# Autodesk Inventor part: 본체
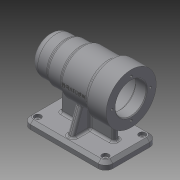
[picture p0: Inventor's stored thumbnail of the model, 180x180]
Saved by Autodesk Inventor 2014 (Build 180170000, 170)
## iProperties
Created: 2016-06
Part Number: 본체
Material: 일반
Document SubType Name: Modeling
Designer: SEC
Density: 1 g/cm^3
Appearance: 기본값
Author: SEC
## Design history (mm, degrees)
sketch "스케치1" dims "d24" = 3
  geometry: L1 (-56, 0)-(56, 0); L2 (-56, 0)-(-56, 15); L3 (-46, 25)-(-31, 25); L4 (-31, 25)-(-31, 27); L5 (-31, 27)-(-11, 27); L6 (-11, 27)-(-11, 30); L7 (-11, 30)-(28, 30); L8 (28, 30)-(28, 34); L9 (28, 34)-(56, 34); L10 (56, 34)-(56, 21); L11 (56, 21)-(41, 21); L12 (41, 21)-(41, 24); L13 (41, 24)-(-13, 24); L14 (-13, 24)-(-13, 21); L15 (-13, 21)-(-25, 21); L16 (-25, 21)-(-25, 17.5); L17 (-25, 17.5)-(-43, 17.5); L18 (-43, 17.5)-(-43, 16); L19 (-43, 16)-(-47, 16); L20 (-47, 16)-(-47, 10.5); L21 (-47, 10.5)-(-50, 10.5); L22 (-50, 10.5)-(-50, 0); A1 r 10 centre (-46, 15) between (-46, 25) and (-56, 15); 3 further points
  constraints: 44 end point, 17 parallel, 4 perpendicular, 3 point on line, 2 point on circle, 2 tangent, 1 centre point, 1 coincident, 1 horizontal, 1 midpoint, 1 vertical alignment
  dimensions: "d0" = 112 distance of L1.start L1.end; "d1" = 42 diameter of L11 L1; "d2" = 48 diameter of L13 L1; "d3" = 42 diameter of L15 L1; "d4" = 35 diameter of L17 L1; "d5" = 32 diameter of L19 L1; "d6" = 21 diameter of L21 L1; "d7" = 15 distance of L10.end L11.end; "d8" = 54 distance of L12.end L13.end; "d9" = 12 distance of L14.end L15.end; "d10" = 18 distance of L16.end L17.end; "d11" = 3 distance of L20.end L21.end; "d12" = 4 distance of L18.end L19.end; "d13" = 25 distance of point (-56, 25) L3.end; "d14" = 45 horizontal distance of L5.end point (-56, 25); "d15" = 84 horizontal distance of L7.end point (-56, 25); "d16" = 68 diameter of L9 L1; "d17" = 60 diameter of L7 L1; "d18" = 54 diameter of L5 L1; "d19" = 50 diameter of L3 L1; "d20" = 10 radius of A1
revolve "회전1" sketch "스케치1" stored, may be unused: angle "d21" = 90 deg
fillet "모깎기1" dims "d22" = 3
fillet "모깎기2" dims "d23" = 0.3
fillet "모깎기3" dims "d24" = 3
fillet "모깎기4" dims "d25" = 3
chamfer "모따기1" distance "d26" = 1; stored, may be unused: second distance "d27" = 2, angle "d28" = 45 deg
node "작업 평면1"
sketch "스케치2"
  geometry: L1 (-56, -35)-(56, -35); L2 (56, -35)-(56, 35); L3 (56, 35)-(-56, 35); L4 (-56, 35)-(-56, -35); L5 (-56, -35)-(56, 35); L6 (56, -35)-(-56, 35); 1 further point
  constraints: 12 end point, 2 midpoint, 2 parallel, 1 horizontal, 1 perpendicular
  dimensions: "d30" = 112 distance of L2.end L3.end; "d31" = 70 distance of L1.end L2.end
extrude "돌출1" join sketch "스케치2" distance "d32" = 10; taper "d33" = 0 deg
hole "구멍1" diameter "d36" = 5; stored, may be unused: countersink angle "d40" = 90 deg, drill point angle "d42" = 0 deg; dims "d34" = 10, "d35" = 10, "d37" = 6, "d38" = 9, "d39" = 4, "d41" = 8
fillet "모깎기5" dims "d43" = 10
chamfer "모따기2" distance "d44" = 4; stored, may be unused: second distance "d45" = 2, angle "d46" = 45 deg
sketch "스케치4"
  geometry: L1 (-60, 29.5)-(-60, 20.5) reference; L2 (-60, -20.5)-(-60, -29.5) reference; L3 (-60, 28)-(-25.68, 15.509); L4 (-25.68, -15.509)-(-60, -28); L5 (-70, 35)-(-64, 35) reference; L6 (-64, -35)-(-70, -35) reference; L7 (-60, 28)-(-60, -28); A1 r 30 centre (0, 0) between (-25.68, 15.509) and (-25.68, -15.509) reference; A2 r 30 centre (0, 0) between (-25.68, 15.509) and (-25.68, -15.509); 1 further point
  constraints: 6 end point, 4 point on circle, 2 point on line, 1 centre point, 1 coincident, 1 concentric, 1 perpendicular
  dimensions: "d50" = 7 distance from line of L3.start L5; "d51" = 7 distance from line of L6 L4.end; "d52" = 110 deg angle of L1 L3; "d53" = 110 deg angle of L2 L4
extrude "돌출2" join sketch "스케치4" stored distance "d54" = 8; taper "d55" = 0 deg
sketch "스케치5"
  geometry: L1 (-46, -60)-(46, -60) reference; L2 (-46, -25)-(-31, -25) reference; L3 (-36, -25)-(-36, -60); L4 (-56, -70)-(-56, -64) reference; 1 further point
  constraints: 2 end point, 2 point on line, 1 perpendicular
  dimensions: "d56" = 20 distance between parallel lines of L4 L3
feature "리브1" sketch "스케치5" dims "d58" = 1, "d59" = 8, "d60" = 0, "d61" = 0, "d62" = 1, "d63" = 1
sketch "스케치7"
  geometry: L1 (4, 28)-(4, -28) reference; L2 (-4, 28)-(4, 28) reference; L3 (4, 4)-(36, 4); L4 (36, 4)-(36, -4); L5 (36, -4)-(4, -4); 2 further points
  constraints: 6 end point, 2 perpendicular, 2 point on line, 1 horizontal alignment, 1 parallel
  dimensions: "d66" = 32 distance of L3.start L3.end; "d67" = 8 distance of L3.end L4.end
extrude "돌출3" join sketch "스케치7" stored distance "d68" = 8; taper "d69" = 0 deg
fillet "모깎기11" dims "d75" = 3
fillet "모깎기12" dims "d76" = 3
sketch "스케치8"
  geometry: C1 r 22 at (0, 0) reference; 1 further point
  constraints: 1 vertical alignment
  dimensions: "d77" = 26 distance of C1.centre point (0, 26)
hole "구멍2" sketch "스케치8" at (0, 26) diameter "d78" = 3.242; stored, may be unused: countersink angle "d82" = 90 deg, drill point angle "d84" = 118 deg; dims "d79" = 8, "d80" = 9, "d81" = 4, "d83" = 11
fillet "모깎기13" dims "d88" = 3
fillet "모깎기14" dims "d89" = 3
fillet "모깎기15" dims "d90" = 3
node "작업 평면2"
sketch "스케치9"
  geometry: L1 (56, -34)-(56, 34) reference; 2 further points
  constraints: 1 horizontal alignment, 1 other
  dimensions: "d92" = 48 distance from line of L1 point (8, 0)
feature "엠보싱1" sketch "스케치9" dims "d12" = 4, "d93" = 0.5, "d94" = 0
node "솔리드1"
mirror "대칭1"
mirror "대칭2"
pattern_circular "원형 패턴1" dims angle "d86" = 360 deg
other parameters: "d91" = 35
